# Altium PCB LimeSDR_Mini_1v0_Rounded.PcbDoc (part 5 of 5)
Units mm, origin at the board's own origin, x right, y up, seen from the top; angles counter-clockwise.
Board outline 69.3 x 52.3 mm, 8 copper layers (Top, L2, L3, L4, L5, L6, L7, Bottom), stack 1.555 mm thick; 371 components, 281 nets, 1644 pads, 778 vias.
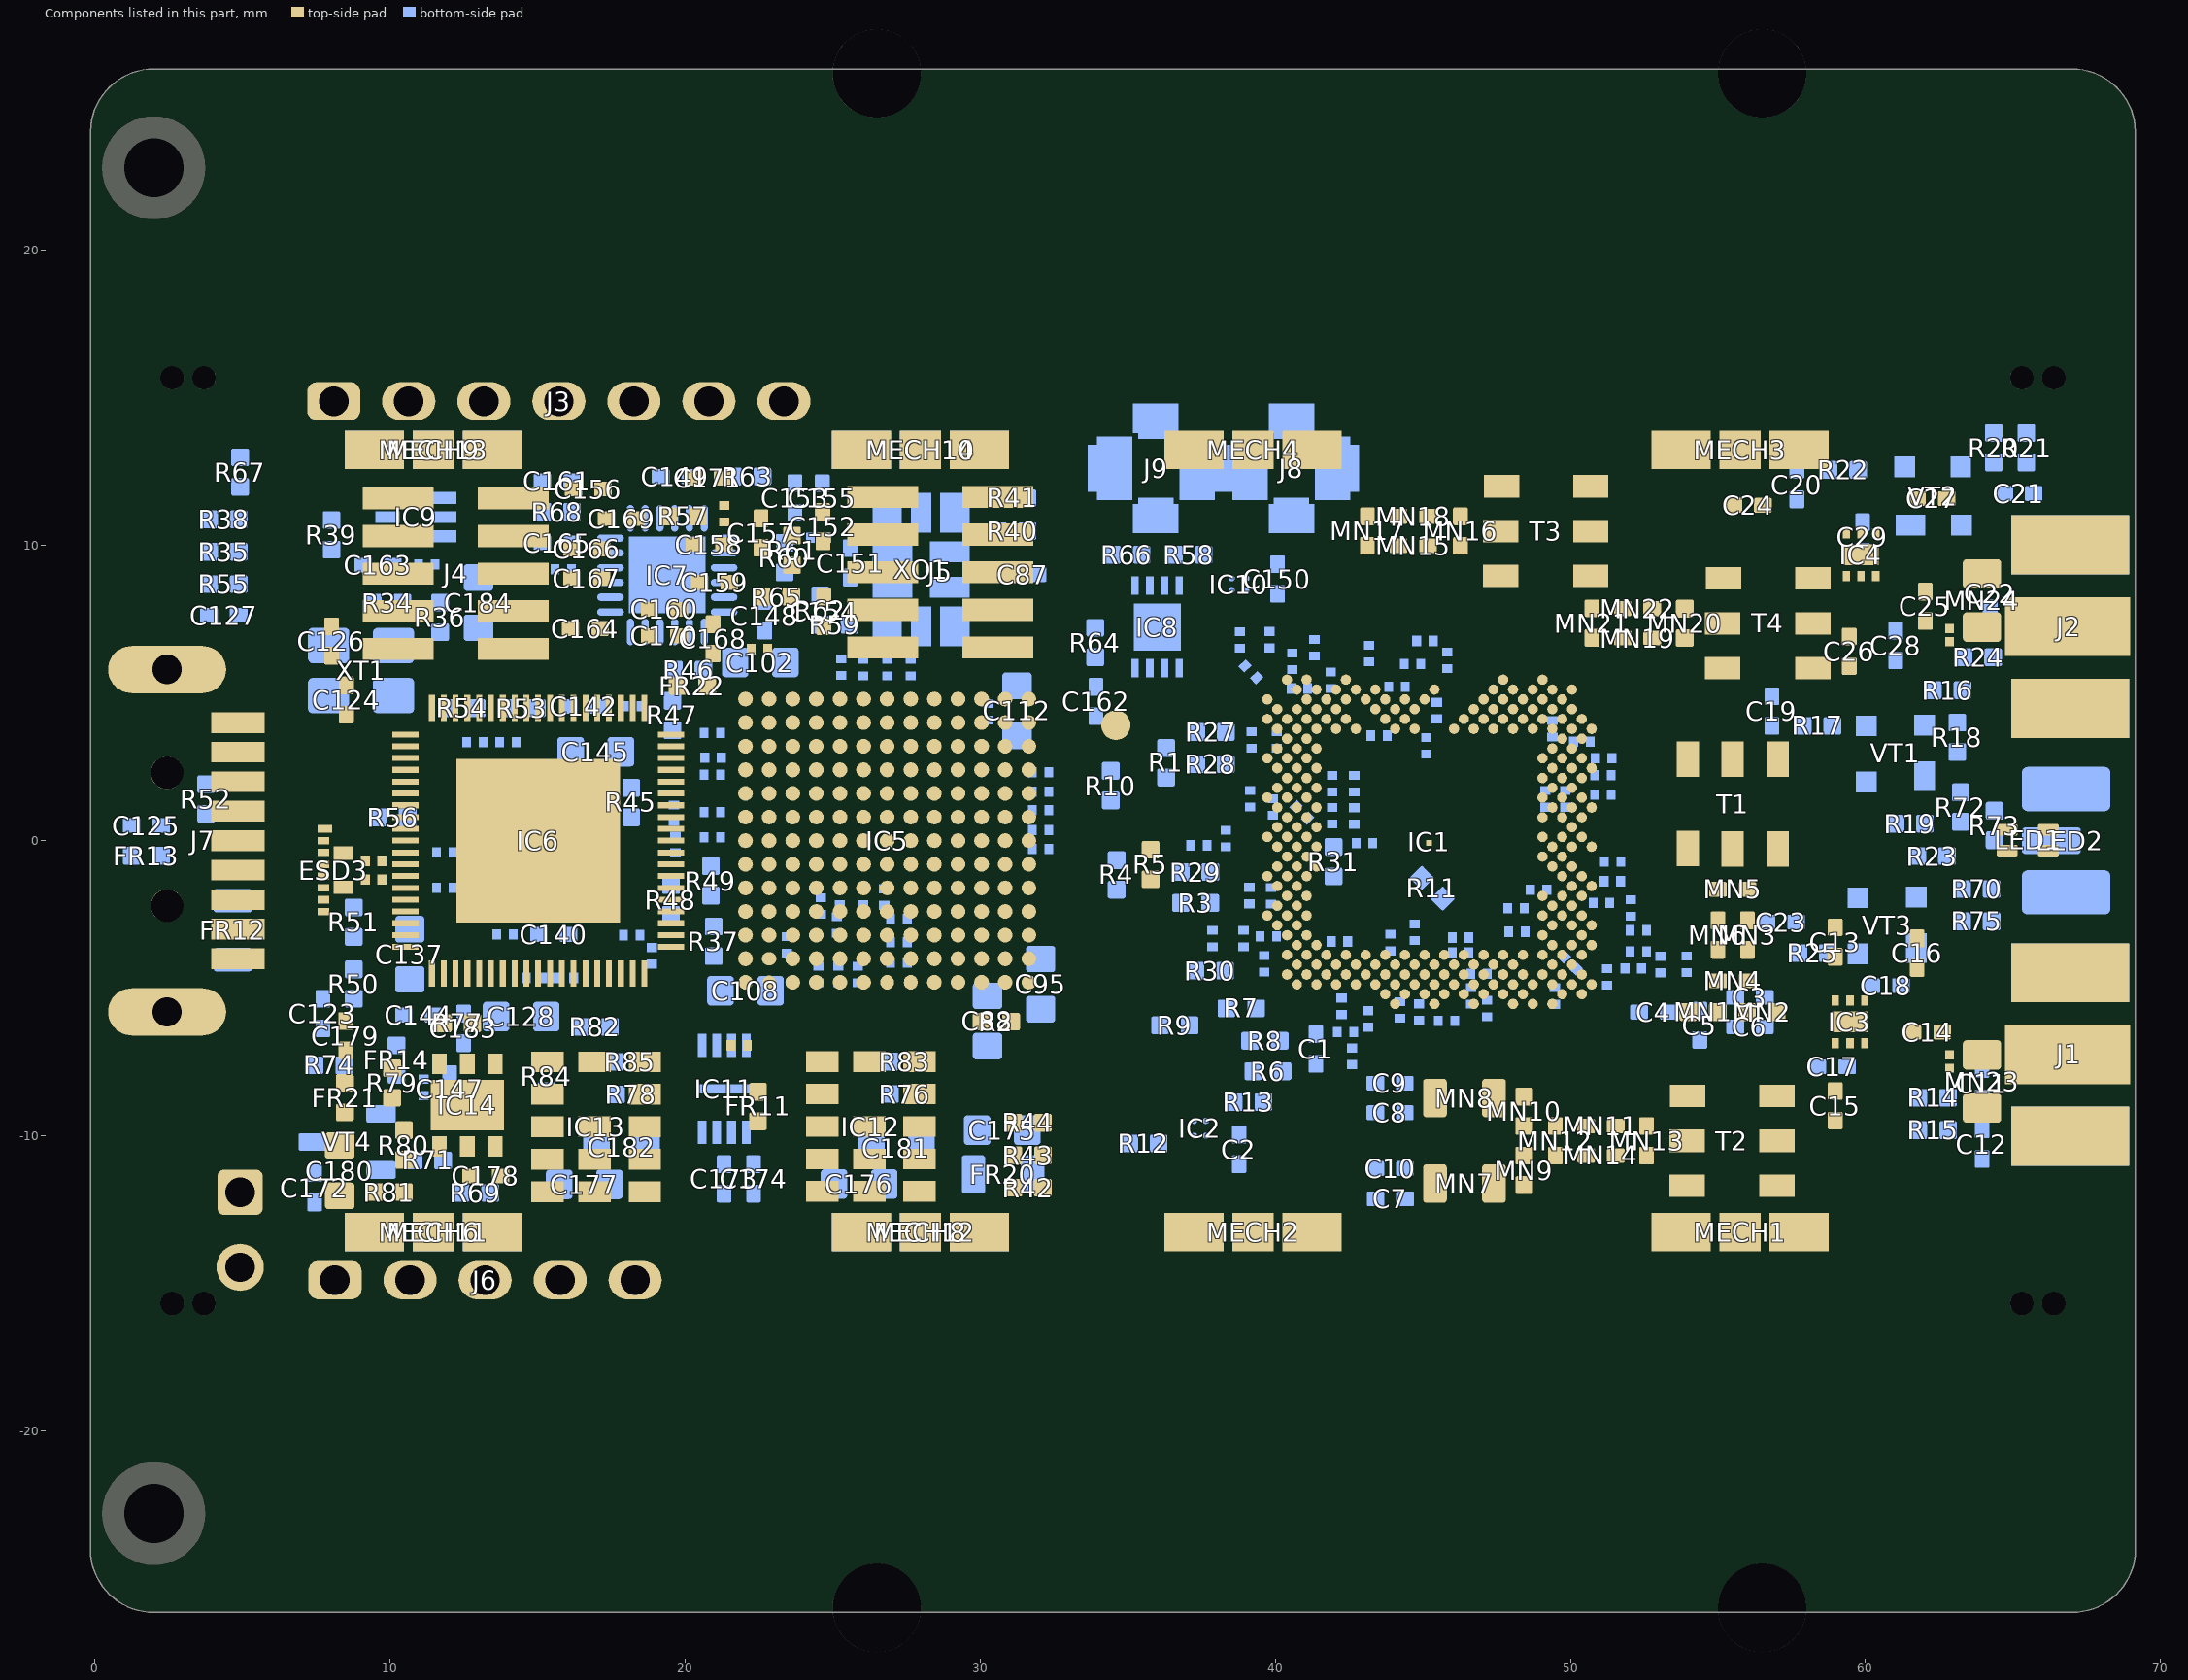
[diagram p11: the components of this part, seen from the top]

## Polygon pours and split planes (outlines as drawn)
GND on L5 "GND_L05_P033" (solid, remove dead copper, pour order 33): 0,-13.685 0,13.685 cw(c2,13.685) 2,15.685 67,15.685 cw(c67,13.685) 69,13.685 69,-13.685 cw(c67,-13.685) 67,-15.685 2,-15.685 cw(c2,-13.685)
VCC1P8_LMS on L5 "VCC1P8_LMS_L05_P026" (solid, remove dead copper, pour order 26): 31.65,-7.335 36.9,-7.335 37.275,-7.71 37.901,-7.71 38.276,-7.335 49.897,-7.335 51.175,-6.057 51.175,2.74 47.875,6.04 39.1,6.04 38.05,7.09 38.05,7.49 38.7,8.14 49.25,8.14 57.25,0.14 57.25,-6.185 55.875,-7.56 55.875,-9.435 52.425,-12.885 35.4,-12.885 31.275,-8.76 31.275,-7.71
GND on L3 "GND_L03_P031" (solid, remove dead copper, pour order 31): 0,-13.685 0,13.685 cw(c2,13.685) 2,15.685 67,15.685 cw(c67,13.685) 69,13.685 69,-13.685 cw(c67,-13.685) 67,-15.685 2,-15.685 cw(c2,-13.685)
VCC3P3 on L3 "VCC3P3_L03_P027" (solid, remove dead copper, pour order 27): 18.625,-11.885 19.756,-11.885 21.45,-10.191 21.45,-2.2 22.99,-0.66 26.65,-0.66 28.475,1.165 28.475,3.717 34.875,10.117 34.875,10.415 34.6,10.69 33.075,10.69 32.525,10.14 28.55,10.14 25.675,7.265 19.7,7.265 16.835,4.4 10.81,4.4 9.65,3.24 9.65,-4.385 11.55,-6.285 12.15,-6.285 14.075,-8.21 14.075,-9.441 15.044,-10.41 17.15,-10.41
VDIO_LMS on L3 "VDIO_LMS_L03_P028" (solid, remove dead copper, pour order 28): 31.05,-12.585 31.05,-9.96 32.625,-8.385 32.625,-7.635 31.525,-6.535 31.525,-2.435 37.475,3.515 38.4,3.515 41.925,-0.01 41.925,-3.635 35.9,-9.66 35.9,-10.26 33.2,-12.96 31.425,-12.96
GND on L2 "GND_L02_P030" (solid, remove dead copper, pour order 30): 0,-13.685 0,13.685 cw(c2,13.685) 2,15.685 67,15.685 cw(c67,13.685) 69,13.685 69,-13.685 cw(c67,-13.685) 67,-15.685 2,-15.685 cw(c2,-13.685)
USB_GND on L2 "USB_GND_L02_P029" (solid, remove dead copper, pour order 29): 10,-6.935 11.175,-5.76 11.175,-2.46 11.175,3.49 10.05,4.615 6.075,4.615 2.125,4.615 1.25,3.74 1.25,-5.185 3,-6.935
no net on Top "Top Layer-No Net" (none, pour order 39): 180,50
GND on Top "Top Layer-No Net" (solid, pour order 37): 0,-23.685 ccw(c2,-23.685) 2,-25.685 67,-25.685 ccw(c67,-23.685) 69,-23.685 69,-15.685 0,-15.685
GND on Top "Top Layer-No Net" (solid, pour order 38): -0.038,-24.244 cw(c0.095,-24.175) -0.055,-24.175 -0.055,24.025 cw(c0.095,24.025) -0.05,24.065 cw(c2.1,24.025) 2.1,26.175 67.09,26.175 cw(c67.09,24.025) 69.24,24.065 cw(c69.095,24.025) 69.245,24.025 69.245,-24.175 cw(c69.095,-24.175) 69.228,-24.244 cw(c67.095,-23.975) 67.095,-26.125 2.095,-26.125 cw(c2.095,-23.975)
GND on L4 "GND_L04_P032" (solid, remove dead copper, pour order 32): 0,-13.685 0,13.685 cw(c2,13.685) 2,15.685 67,15.685 cw(c67,13.685) 69,13.685 69,-13.685 cw(c67,-13.685) 67,-15.685 2,-15.685 cw(c2,-13.685)
GND on L6 "GND_L06_P034" (solid, remove dead copper, pour order 34): 0,-13.685 0,13.685 cw(c2,13.685) 2,15.685 67,15.685 cw(c67,13.685) 69,13.685 69,-13.685 cw(c67,-13.685) 67,-15.685 2,-15.685 cw(c2,-13.685)
GND on L7 "GND_L07_P035" (solid, remove dead copper, pour order 35): 0,-13.685 0,13.685 cw(c2,13.685) 2,15.685 67,15.685 cw(c67,13.685) 69,13.685 69,-13.685 cw(c67,-13.685) 67,-15.685 2,-15.685 cw(c2,-13.685)
GND on Bottom "GND_L08_P036" (solid, remove dead copper, pour order 36): 0,-13.685 0,13.685 cw(c2,13.685) 2,15.685 67,15.685 cw(c67,13.685) 69,13.685 69,-13.685 cw(c67,-13.685) 67,-15.685 2,-15.685 cw(c2,-13.685)
no net on TopSolder "Top Layer-No Net" (none): 0,-23.685 ccw(c2,-23.685) 2,-25.685 67,-25.685 ccw(c67,-23.685) 69,-23.685 69,-15.685 0,-15.685
no net on Mechanical2 "Top Layer-No Net" (none): 180,50
no net on Mechanical2 "Top Layer-No Net" (none): 102,48
no net on Mechanical2 "Top Layer-No Net" (none): 102,48
no net on Mechanical2 "Top Layer-No Net" (none): 102,48

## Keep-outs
KeepOutLayer:
  lines w0.1: 113.85,-33.86 ccw(c115.85,-33.86) 115.85,-35.86 180.85,-35.86 ccw(c180.85,-33.86) 182.85,-33.86 182.85,-25.86 113.85,-25.86 113.85,-33.86
  lines w0.3: -22.525,55.85 -22.525,104.05 ; -22.525,56.05 ccw(c-20.525,56.05) -20.525,54.05 44.475,54.05 ccw(c44.475,56.05) 46.475,56.05 ; -22.52,104.05 cw(c-20.52,104.05) -20.52,106.05 44.47,106.05 cw(c44.47,104.05) 46.47,104.05 ; 0,-24.2 0,24 ; 0,-24 ccw(c2,-24) 2,-26 67,-26 ccw(c67,-24) 69,-24 ; 0.005,24 cw(c2.005,24) 2.005,26 66.995,26 cw(c66.995,24) 68.995,24 ; 46.475,55.85 46.475,104.05 ; 69,-24.2 69,24 ; 113.85,13.51 cw(c115.85,13.51) 115.85,15.51 ; 115.855,15.515 180.845,15.515 ; 180.85,15.51 cw(c180.85,13.51) 182.85,13.51

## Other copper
Top:
  region net GND: 64.7,-9.01 64.7,-12.485 67.55,-12.485 68.95,-11.085 68.95,-9.01
  region net GND: 64.7,5.49 64.7,2.29 68.071,2.29 68.95,3.169 68.95,5.49
  region net GND: 64.7,9.015 64.7,12.49 67.55,12.49 68.95,11.09 68.95,9.015
  region net GND: 64.7,-5.485 64.7,-2.01 67.55,-2.01 68.95,-3.41 68.95,-5.485
  region net NetC21_2: 63.3,9.34 63.3,9.565 64.125,10.39 64.4,10.39 64.6,10.19 64.6,9.34
  region net NetC11_2: 63.3,-9.36 63.3,-9.71 63.475,-9.885 64.425,-9.885 64.6,-9.71 64.6,-9.36
  region net GND: 52.9,3.865 52.9,1.657 54.642,1.657 54.642,3.865
  region net VDIO_LMS: 8.8,-8.91 8.1,-8.91 7.8,-9.21 7.8,-10.085 8.8,-10.085
  region net GND: 13.025,-7.21 13.175,-7.36 13.175,-8.11 13.925,-8.11 13.925,-9.81 11.375,-9.81 11.375,-8.11 12.15,-8.11 12.15,-7.21
  region net VCC3P3: 14.575,-9.46 14.575,-10.035 13.9,-10.71 13.325,-10.71 13.325,-10.01 13.9,-10.01 14.125,-9.785 14.125,-9.46
  region net VCC3P3: 12.5,-6.535 12.525,-6.535 13.325,-7.335 13.325,-7.91 13.875,-7.91 14.075,-8.11 14.075,-9.96 14.575,-9.46 14.575,-8.035 14.05,-7.51 14.05,-6.86 13.025,-5.835 12.5,-5.835
  region net GND: 56.845,-7.685 55.96,-8.57 55.96,-8.795 56.21,-9.045 57.785,-9.045 58.035,-8.795 58.035,-8.57 57.15,-7.685
  region net GND: 49.15,12.99 49.55,12.59 49.55,12.015 49.95,11.615 51.425,11.615 52.175,12.365 52.175,12.99
  region net GND: 57.925,9.715 57.175,8.965 57.175,8.74 57.425,8.49 58.825,8.49 58.825,9.665 58.775,9.715
  pour cut-out: 43.477,-13.01 42.1,-11.633 42.1,-7.51 43.1,-6.51 44.1,-6.51 45.925,-4.685 48.54,-4.685 49.515,-5.66 51.65,-5.66 52.525,-4.785 52.525,0.94 53.075,1.49 54.6,1.49 54.825,1.715 54.825,4.215 54.325,4.715 51.96,4.715 50.66,3.415 45.45,3.415 45.45,4.715 43.325,6.84 40.9,6.84 40.125,7.615 40.125,11.09 42.025,12.99 63.8,12.99 66.275,10.515 69,10.515 69,3.015 64.75,3.015 64.35,2.615 63.6,2.615 62,1.015 62,-0.685 63.625,-2.31 64.35,-2.31 65.45,-3.41 69,-3.41 69,-6.96 69,-10.535 66.25,-10.535 63.775,-13.01
  region net VDIO_LMS: 7.8,-10.61 7.8,-11.285 7.925,-11.41 8.675,-11.41 8.8,-11.285 8.8,-10.61
  region net VCC1P8: 21.125,11.19 20.95,11.365 20.95,11.89 21,11.94 21.875,11.94 21.925,11.89 21.925,11.39 21.725,11.19
  pour cut-out: 5.075,-4.46 9.075,-4.46 10.325,-3.21 10.325,3.015 8.15,3.015 6.58,1.445 5.855,1.445 5.075,0.665
  region net VCC1P8_LMS: 45.825,-12.277 44.8,-12.277 44.625,-12.102 44.625,-11.152 44.825,-10.952 45.825,-10.952
  region net VCC1P8_LMS: 45.825,-8.06 44.8,-8.06 44.625,-8.235 44.625,-9.185 44.825,-9.385 45.825,-9.385
  region net VCC3P3A: 21.95,-8.835 22.125,-9.01 22.875,-9.01 23.2,-8.685 23.2,-6.76 23.075,-6.635 22.075,-6.635 21.95,-6.76
  region net PG_VCC1P8: 27.386,-8.945 28.736,-8.945 28.936,-8.745 28.936,-8.585 27.386,-8.585
  region net PG_VCC1P8: 27.386,-8.225 28.736,-8.225 28.936,-8.425 28.936,-8.585 27.386,-8.585
  region net NetIC12_11: 27.386,-7.845 28.736,-7.845 28.936,-7.645 28.936,-7.485 27.386,-7.485
  region net NetIC12_11: 27.386,-7.125 28.736,-7.125 28.936,-7.325 28.936,-7.485 27.386,-7.485
  region net VCC5P0_USB: 25.214,-10.425 23.864,-10.425 23.664,-10.625 23.664,-10.785 25.214,-10.785
  region net VCC5P0_USB: 25.214,-11.145 23.864,-11.145 23.664,-10.945 23.664,-10.785 25.214,-10.785
  region net VCC5P0_USB: 25.214,-11.525 23.864,-11.525 23.664,-11.725 23.664,-11.885 25.214,-11.885
  region net VCC5P0_USB: 25.214,-12.245 23.864,-12.245 23.664,-12.045 23.664,-11.885 25.214,-11.885
  region net VCC5P0_USB: 23.864,-11.145 23.864,-11.525 25.214,-11.525 25.214,-11.145
  region net VCC1P8: 28.736,-11.145 28.736,-11.525 27.386,-11.525 27.386,-11.145
  region net VCC1P8: 27.386,-12.245 28.736,-12.245 28.936,-12.045 28.936,-11.885 27.386,-11.885
  region net VCC1P8: 27.386,-11.525 28.736,-11.525 28.936,-11.725 28.936,-11.885 27.386,-11.885
  region net VCC1P8: 27.386,-11.145 28.736,-11.145 28.936,-10.945 28.936,-10.785 27.386,-10.785
  region net VCC1P8: 27.386,-10.425 28.736,-10.425 28.936,-10.625 28.936,-10.785 27.386,-10.785
  region net NetIC13_10: 18.075,-8.955 19.425,-8.955 19.625,-8.755 19.625,-8.595 18.075,-8.595
  region net NetIC13_10: 18.075,-8.235 19.425,-8.235 19.625,-8.435 19.625,-8.595 18.075,-8.595
  region net NetIC13_11: 18.075,-7.855 19.425,-7.855 19.625,-7.655 19.625,-7.495 18.075,-7.495
  region net NetIC13_11: 18.075,-7.135 19.425,-7.135 19.625,-7.335 19.625,-7.495 18.075,-7.495
  region net NetIC13_1: 15.903,-7.135 14.553,-7.135 14.353,-7.335 14.353,-7.495 15.903,-7.495
  region net NetIC13_1: 15.903,-7.855 14.553,-7.855 14.353,-7.655 14.353,-7.495 15.903,-7.495
  region net VCC5P0_USB: 15.903,-10.435 14.553,-10.435 14.353,-10.635 14.353,-10.795 15.903,-10.795
  region net VCC5P0_USB: 15.903,-11.155 14.553,-11.155 14.353,-10.955 14.353,-10.795 15.903,-10.795
  region net VCC5P0_USB: 15.903,-11.535 14.553,-11.535 14.353,-11.735 14.353,-11.895 15.903,-11.895
  region net VCC5P0_USB: 15.903,-12.255 14.553,-12.255 14.353,-12.055 14.353,-11.895 15.903,-11.895
  region net VCC5P0_USB: 14.553,-11.155 14.553,-11.535 15.903,-11.535 15.903,-11.155
  region net VCC3P3: 19.425,-11.155 19.425,-11.535 18.075,-11.535 18.075,-11.155
  region net VCC3P3: 18.075,-12.255 19.425,-12.255 19.625,-12.055 19.625,-11.895 18.075,-11.895
  region net VCC3P3: 18.075,-11.535 19.425,-11.535 19.625,-11.735 19.625,-11.895 18.075,-11.895
  region net VCC3P3: 18.075,-11.155 19.425,-11.155 19.625,-10.955 19.625,-10.795 18.075,-10.795
  region net VCC3P3: 18.075,-10.435 19.425,-10.435 19.625,-10.635 19.625,-10.795 18.075,-10.795
  region net USB_VBUS: 5.75,-3.36 3.975,-3.36 3.8,-3.535 3.225,-3.535 3,-3.31 3,-3.01 5.75,-3.01
  region net USB_VBUS: 5.75,-2.64 3.975,-2.64 3.8,-2.465 3.225,-2.465 3,-2.69 3,-2.99 5.75,-2.99
  region net USB_VBUS: 3,-3.31 3,-2.69 4.28,-2.69 4.3,-2.71 4.3,-3.285 4.275,-3.31
  region net GND: 25.375,-12.66 25.375,-12.01 25.5,-11.885 27.15,-11.885 27.15,-12.66
  region net GND: 25.375,-6.579 25.375,-7.36 25.5,-7.485 27.15,-7.485 27.15,-6.579
  region net GND: 16.064,-6.589 16.064,-7.37 16.189,-7.495 17.839,-7.495 17.839,-6.589
  region net GND: 16.011,-12.887 16.011,-12.022 16.136,-11.897 17.786,-11.897 17.786,-12.887
  region net GND: 48.675,-1.538 49.453,-1.538 49.475,-1.56 49.475,-1.36 48.7,-0.585 48.675,-0.585
  region net NetJ7_7: 4.85,0.34 4.025,0.34 3.875,0.49 3.625,0.49 3.525,0.39 3.525,0 4.85,0
  region net NetJ7_7: 4.85,-0.34 4.025,-0.34 3.875,-0.49 3.625,-0.49 3.525,-0.39 3.525,0 4.85,0
  region net TX1_1_A_P: 48.48,-5.778 48.427,-5.725 48.427,-5.583
  region net GND: 21.45,-4.41 21.45,-4.8 22.05,-4.8 21.66,-4.41
  region net NetIC14_4: 9.725,-8.41 9.725,-9.71 10.325,-10.31 10.75,-10.31 11.175,-10.735 11.925,-10.735 12,-10.66 12,-10.085 11.9,-9.985 11.375,-9.985 10.425,-9.035 10.425,-8.41
  region net VDIO_LMS_FPGA: 10.375,-8.01 10.375,-7.16 10.025,-6.81 8.175,-6.81 8.175,-8.21 8.475,-8.51 8.825,-8.51 9.325,-8.01
  region net VCC1P8_LMS: 53.675,-5.46 53.85,-5.285 54.12,-5.285 54.293,-5.458 54.293,-5.808 53.677,-5.808
  region net VCC1P8_LMS: 53.675,-6.156 53.854,-6.335 54.116,-6.335 54.293,-6.158 54.293,-5.808 53.677,-5.808
  region net VCC1P8_LMS: 57.31,-6.156 57.131,-6.335 56.87,-6.335 56.693,-6.158 56.693,-5.808 57.308,-5.808
  region net VCC1P8_LMS: 57.31,-5.46 57.135,-5.285 56.866,-5.285 56.693,-5.458 56.693,-5.808 57.308,-5.808
  region net GND: 63,-7.56 63.2,-7.76 63.2,-8.135 63.1,-8.235 62.7,-8.235 62.55,-8.085 62.55,-7.71 62.7,-7.56
  region net GND: 62.275,6.44 62.025,6.44 61.9,6.315 61.9,6.09 61.975,6.015 62.475,6.015 63.075,6.615 63.075,6.89 62.65,6.89 62.65,6.815
  region net GND: 3.4,3.365 5.75,3.365 5.75,2.64 3.4,2.64
L2:
  pour cut-out: 64.72,-6.248 64.72,-8.248 69,-8.248 69,-6.248
  pour cut-out: 63.3,6.74 63.3,7.74 64.6,7.74 64.6,6.74
  pour cut-out: 63.3,-7.76 63.3,-6.76 64.6,-6.76 64.6,-7.76
  pour cut-out: 46.575,9.68 45.96,9.68 45.96,10.305 46.575,10.305
  pour cut-out: 43.385,9.68 42.86,9.68 42.86,10.305 43.385,10.305
  pour cut-out: 43.385,11.3 42.86,11.3 42.86,10.675 43.385,10.675
  pour cut-out: 45.485,10.25 45.485,9.725 44.86,9.725 44.86,10.25
  pour cut-out: 43.865,10.25 43.865,9.725 44.49,9.725 44.49,10.25
  pour cut-out: 45.485,11.25 45.485,10.725 44.86,10.725 44.86,11.25
  pour cut-out: 43.865,11.25 43.865,10.725 44.49,10.725 44.49,11.25
  pour cut-out: 46.575,10.68 45.96,10.68 45.96,11.305 46.575,11.305
  pour cut-out: 54.15,7.555 53.535,7.555 53.535,8.18 54.15,8.18
  pour cut-out: 64.72,8.252 64.72,6.252 69,6.252 69,8.252
  pour cut-out: 57.59,5.451 57.59,6.251 58.815,6.251 58.815,5.451
  pour cut-out: 54.555,5.45 54.555,6.25 55.78,6.25 55.78,5.45
  pour cut-out: 54.58,8.49 54.58,9.29 55.805,9.29 55.805,8.49
  pour cut-out: 56.625,0.325 57.425,0.325 57.425,-0.9 56.625,-0.9
  pour cut-out: 53.585,0.35 54.385,0.35 54.385,-0.875 53.585,-0.875
  pour cut-out: 56.625,3.375 57.425,3.375 57.425,2.15 56.625,2.15
  pour cut-out: 57.61,-11.295 57.61,-12.095 56.385,-12.095 56.385,-11.295
  pour cut-out: 54.56,-11.295 54.56,-12.095 53.335,-12.095 53.335,-11.295
  pour cut-out: 54.585,-8.255 54.585,-9.055 53.36,-9.055 53.36,-8.255
  pour cut-out: 51.3,9.365 51.3,8.565 50.075,8.565 50.075,9.365
  pour cut-out: 48.275,12.405 48.275,11.605 47.05,11.605 47.05,12.405
  pour cut-out: 48.25,9.365 48.25,8.565 47.025,8.565 47.025,9.365
  region net USB_GND: 5.892,-6.935 10,-6.935 10.239,-6.696 10.239,-6.274 10.15,-6.185 5.825,-6.185 5.825,-6.868
  region net GND: 4.95,-7.685 4.95,-8.935 10.625,-8.935 10.625,-7.685
  pour cut-out: 48.125,-9.36 48.125,-9.985 48.75,-9.985 48.75,-9.36
  pour cut-out: 48.125,-10.36 48.125,-10.985 48.75,-10.985 48.75,-10.36
  pour cut-out: 49.225,-10.98 49.75,-10.98 49.75,-10.355 49.225,-10.355
  pour cut-out: 49.225,-9.36 49.75,-9.36 49.75,-9.985 49.225,-9.985
  pour cut-out: 52.325,-9.36 52.85,-9.36 52.85,-9.985 52.325,-9.985
  pour cut-out: 52.325,-10.98 52.85,-10.98 52.85,-10.355 52.325,-10.355
  pour cut-out: 50.225,-9.93 50.225,-9.405 50.85,-9.405 50.85,-9.93
  pour cut-out: 51.845,-9.93 51.845,-9.405 51.22,-9.405 51.22,-9.93
  pour cut-out: 50.225,-10.93 50.225,-10.405 50.85,-10.405 50.85,-10.93
  pour cut-out: 51.845,-10.93 51.845,-10.405 51.22,-10.405 51.22,-10.93
  pour cut-out: 56.26,-2.39 55.735,-2.39 55.735,-3.015 56.26,-3.015
  pour cut-out: 56.26,-4.01 55.735,-4.01 55.735,-3.385 56.26,-3.385
  pour cut-out: 55.26,-2.39 54.735,-2.39 54.735,-3.015 55.26,-3.015
  pour cut-out: 55.26,-4.01 54.735,-4.01 54.735,-3.385 55.26,-3.385
  pour cut-out: 56.31,-1.91 56.31,-1.385 55.685,-1.385 55.685,-1.91
  pour cut-out: 54.69,-1.91 54.69,-1.385 55.315,-1.385 55.315,-1.91
  pour cut-out: 54.69,-5.01 54.69,-4.485 55.315,-4.485 55.315,-5.01
  pour cut-out: 56.31,-5.01 56.31,-4.485 55.685,-4.485 55.685,-5.01
  pour cut-out: 55.69,-6.11 56.315,-6.11 56.315,-5.485 55.69,-5.485
  pour cut-out: 54.69,-6.11 55.315,-6.11 55.315,-5.485 54.69,-5.485
  pour cut-out: 51.44,8.125 51.44,7.6 52.065,7.6 52.065,8.125
  pour cut-out: 53.06,8.125 53.06,7.6 52.435,7.6 52.435,8.125
  pour cut-out: 51.44,7.125 51.44,6.6 52.065,6.6 52.065,7.125
  pour cut-out: 53.06,7.125 53.06,6.6 52.435,6.6 52.435,7.125
  pour cut-out: 50.96,8.175 50.435,8.175 50.435,7.55 50.96,7.55
  pour cut-out: 50.96,6.555 50.435,6.555 50.435,7.18 50.96,7.18
  pour cut-out: 54.15,6.555 53.535,6.555 53.535,7.18 54.15,7.18
L3:
  pour cut-out: 64.72,-6.248 64.72,-8.248 69,-8.248 69,-6.248
  pour cut-out: 63.3,6.74 63.3,7.74 64.6,7.74 64.6,6.74
  pour cut-out: 63.3,-7.76 63.3,-6.76 64.6,-6.76 64.6,-7.76
  pour cut-out: 64.72,8.252 64.72,6.252 69,6.252 69,8.252
  region net VCC5P0_USB: 5.075,-5.31 5.175,-5.41 5.975,-5.41 6.075,-5.31 6.075,-4.66 5.625,-4.21 5.075,-4.21
  region net VCC3P3A: 22.375,-7.11 23.15,-7.11 23.2,-7.06 23.2,-6.685 22.7,-6.185 22.475,-6.185 22.325,-6.335 22.325,-7.06
L4:
  pour cut-out: 64.72,-6.248 64.72,-8.248 69,-8.248 69,-6.248
  pour cut-out: 64.72,8.252 64.72,6.252 69,6.252 69,8.252
L5:
  pour cut-out: 64.72,-6.248 64.72,-8.248 68.92,-8.248 68.92,-6.248
  pour cut-out: 64.72,8.252 64.72,6.252 68.92,6.252 68.92,8.252
  region net AVDD_FT: 10.975,-6.535 10.85,-6.66 10.85,-7.56 10.975,-7.685 11.375,-7.685 11.5,-7.56 11.5,-6.66 11.375,-6.535
  text "A" at 0.575,-8.36 h0.7
  text "V" at 1.575,-8.36 h0.7
  text "L" at 1.05,-8.935 h0.7
  text "D" at 0.8,-10.56 h0.7
  text "R" at 1.35,-10.56 h0.7
L7:
  pour cut-out: 26.35,7.94 26.35,6.677 26.437,6.59 27.35,6.59 27.35,7.94
L6:
  region net VCC1P8: 21.075,11.515 20.95,11.64 20.95,11.815 21.437,12.302 21.825,11.915 21.825,11.615 21.725,11.515
  region net VCC3P3A: 22.375,-7.11 23.15,-7.11 23.2,-7.06 23.2,-6.685 22.7,-6.185 22.475,-6.185 22.25,-6.41 22.25,-6.985
Bottom:
  region net GND: 64.598,-9.08 64.598,-8.764 68.95,-8.764 68.95,-9.08
  region net GND: 64.691,-9.08 64.691,-11.272 68.95,-11.272 68.95,-9.08
  region net GND: 64.691,-3.224 64.691,-5.732 68.95,-5.732 68.95,-3.224
  region net GND: 64.598,5.42 64.598,5.736 68.95,5.736 68.95,5.42
  region net GND: 11.8,-5.323 11.562,-5.56 11.175,-5.56 11.175,-6.26 11.275,-6.36 12.85,-6.36 12.875,-6.335 12.875,-5.685 12.85,-5.685 12.7,-5.535 12.177,-5.535 12.009,-5.366
  region net VCC1P8_LMS: 44.042,-9.393 44.133,-9.485 44.892,-9.485 45.1,-9.277 45.1,-8.718 44.042,-8.718
  region net VCC1P8_LMS: 44.042,-8.043 44.125,-7.96 44.9,-7.96 45.1,-8.16 45.1,-8.718 44.042,-8.718
  region net VCC5P0_USB: 13.1,-11.585 14.3,-11.585 14.438,-11.448 14.575,-11.448 14.575,-12.105 14.395,-12.285 13.1,-12.285
  region net AVDD_FT: 9.925,-8.235 12.225,-8.235 12.275,-8.185 12.275,-7.479 11.459,-6.785 11.025,-6.785 10.95,-6.86 10.95,-7.26 10.8,-7.41 9.875,-7.41 9.875,-8.185
  region net GND: 10.017,-11.86 8.9,-11.86 8.9,-11.163 8.84,-11.103 9.083,-10.86 10.385,-10.86 10.385,-11.492
  region net NetC50_1: 51.875,-2.86 51.625,-3.11 50.346,-3.11 50.346,-3.281 51.025,-3.96 52.2,-3.96 52.2,-2.86
  region net GND: 20.18,-8.56 20.18,-9.19 20.25,-9.26 20.675,-9.26 20.75,-9.185 20.75,-8.935 20.95,-8.735 22.55,-8.735 22.875,-8.41 22.875,-8.185 21.24,-8.185 20.968,-7.914
  region net VCC3P3: 21.05,2.065 21.05,2.99 20.875,3.165 21.248,3.165 21.345,3.068 21.345,2.38 21.345,2.065
  region net GND: 15.639,10.777 15.639,10.604 15.475,10.44 15.25,10.44 15.2,10.49 15.2,10.64 15.225,10.665 15.527,10.665
  region net GND: 8.925,9.09 8.8,9.215 8.8,9.34 8.725,9.415 8.425,9.415 8.177,9.167 8.177,10.015 9.4,10.015 9.4,9.09
  region net GND: 25.05,5.015 24.7,5.015 24.025,5.69 24.025,6.415 24.2,6.59 26.05,6.59 26.225,6.415 27.475,6.415 27.475,5.99 24.975,5.99 24.85,5.865 24.85,5.2 25.04,5.2 25.05,5.19
  region net GND: 18.15,6.948 18.65,6.948 18.65,8.065 18.15,7.565 18.15,7.088
  region net GND: 20.125,7.765 20.5,7.39 20.5,6.565 20.85,6.215 21.875,6.215 21.95,6.29 21.95,7.04 21.525,7.465 20.925,7.465 20.625,7.765
  region net GND: 20.18,-8.006 20.18,-8.56 21.5,-8.56 21.5,-8.485 20.95,-7.935 20.251,-7.935
  region net VCC3P3: 19.6,-12.08 19.9,-11.78 19.9,-10.18 19.6,-9.88
  region net GND: 27.55,6.549 27.55,6.245 27.65,6.145 27.042,6.141 27.125,6.245 27.45,6.245 27.45,6.549
  region net VCC1P8_LMS: 31.375,-12.06 32.175,-12.06 32.5,-11.735 32.5,-7.835 32.05,-7.385 31.375,-7.385 30.925,-7.835 30.925,-11.61
  region net VCC1P8: 28.34,-12.11 30.125,-12.11 30.35,-11.885 30.35,-10.86 30.025,-10.535 29.275,-10.535 28.3,-9.56 27.575,-9.56 27.575,-11.345
  region net VDIO_LMS_LMK: 16.55,8.59 16.95,8.59 17.075,8.465 17.8,8.465 17.925,8.34 17.925,8.19 17.85,8.115 16.925,8.115 16.85,8.19 16.6,8.19 16.5,8.29 16.5,8.54
  region net VDIO_LMS: 35.425,-1.035 35.425,-0.61 35.55,-0.485 35.95,-0.485 36.225,-0.76 36.225,-1.035
  region net USB_VBUS: 5.75,-2.01 5.375,-1.635 3.975,-1.635 3.55,-1.635 3.125,-2.06 3.125,-2.485 3,-2.61 3,-3.41 3.125,-3.535 3.825,-3.535 4.15,-3.21 5.625,-3.21 5.75,-3.335
  region net VCC5P0_USB: 4.025,-3.635 4.025,-4.76 4.75,-5.485 5.825,-5.485 5.975,-5.335 5.975,-4.11 5.5,-3.635
  region net USB_VBUS: 5.75,-3.335 5.95,-3.335 7.05,-4.435 7.75,-4.435 8.125,-4.06 8.125,-2.56 7.575,-2.01 5.75,-2.01
  pour cut-out: 4.25,-1.685 4.25,3.815 4.75,4.315 8.25,4.315 8.75,3.815 8.75,-1.435 8.25,-1.935 4.5,-1.935
  region net NetC45_1: 38.251,6.397 38.251,6.039 38.63,5.66 38.988,5.66
  region net VCC1P8_LMS: 53.025,-5.46 53.208,-5.277 54.108,-5.277 54.283,-5.452 54.283,-5.81 53.025,-5.81
  region net VCC1P8_LMS: 53.025,-6.16 53.208,-6.343 54.108,-6.343 54.407,-6.045 54.407,-5.81 53.025,-5.81
  region net VCC1P8_LMS: 44.042,-10.943 44.125,-10.86 44.9,-10.86 45.1,-11.06 45.1,-11.618 44.042,-11.618
  region net USB_VBUS: 7.8,-3.735 8.125,-4.06 8.125,-4.56 8.625,-5.06 9.125,-5.06 9.275,-5.21 9.275,-5.71 9.125,-5.86 7.45,-5.86 6.725,-5.135 6.725,-3.735
  region net VDIO_LMS: 37.091,2.374 36.55,2.915 36.55,3.54 37.046,4.036 37.626,4.036 37.775,3.887 37.775,3.013
  region net VCC5P0_USB: 14.525,-10.555 14.525,-9.935 15.05,-9.41 15.375,-9.41 15.95,-9.985 15.95,-10.555
  region net VCC5P0_USB: 25.486,-10.77 25.261,-10.545 23.836,-10.545 23.686,-10.695 23.686,-11.995 23.836,-12.145 25.311,-12.145 25.486,-11.97
  region net NetIC12_11: 27.636,-7.125 28.736,-7.125 28.936,-7.325 28.936,-7.485 27.636,-7.485
  region net NetIC12_11: 27.636,-7.845 28.736,-7.845 28.936,-7.645 28.936,-7.485 27.636,-7.485
  region net PG_VCC1P8: 27.575,-8.945 28.736,-8.945 28.936,-8.745 28.936,-8.585 27.575,-8.585
  region net PG_VCC1P8: 27.575,-8.225 28.736,-8.225 28.936,-8.425 28.936,-8.585 27.575,-8.585
  region net VCC5P0_USB: 16.175,-10.78 15.95,-10.555 14.525,-10.555 14.375,-10.705 14.375,-12.005 14.525,-12.155 16,-12.155 16.175,-11.98
  region net NetIC13_11: 18.325,-7.135 19.425,-7.135 19.625,-7.335 19.625,-7.495 18.325,-7.495
  region net NetIC13_11: 18.325,-7.855 19.425,-7.855 19.625,-7.655 19.625,-7.495 18.325,-7.495
  region net NetIC13_10: 18.264,-8.955 19.425,-8.955 19.625,-8.755 19.625,-8.595 18.264,-8.595
  region net NetIC13_10: 18.264,-8.235 19.425,-8.235 19.625,-8.435 19.625,-8.595 18.264,-8.595
  region net VCC3P3: 18.975,-9.255 19.6,-9.88 19.6,-12.08 19.175,-12.505 18.25,-12.505 18.25,-9.28 18.275,-9.255
  region net NetC163_1: 9.5,10.515 9.5,9.34 9.75,9.09 11.075,9.09 11.175,9.19 11.175,9.815 10.475,10.515
  region net GND: 44.851,4.147 45.001,4.297 45.601,4.297 45.601,3.972 45.426,3.797 44.976,3.797
  region net NetC75_1: 44.676,4.922 44.676,5.447 44.776,5.547 45.051,5.547 45.076,5.522 45.076,5.222 44.851,4.997 44.733,4.879
  region net VDIO_LMS: 41.226,-1.453 41.776,-0.903 42.026,-0.903 42.026,-1.428 41.626,-1.828 41.426,-1.828 41.226,-1.628
  region net GND: 40.398,2.802 40.398,1.969 40.201,1.772 39.276,1.772 39.251,1.797 39.251,2.997 39.351,3.097 40.102,3.097
  region net GND: 45.976,-2.303 45.976,-2.828 47.601,-2.828 47.601,-2.303
  region net NetC45_1: 38.988,5.66 39.501,6.172 39.501,6.472 39.501,6.597 39.401,6.697 38.276,6.697 38.251,6.672 38.251,6.397
  region net VCC3P3: 15.225,-5.36 14.975,-5.11 14.975,-4.46 15.85,-4.46 15.85,-5.11 15.6,-5.36
  region net VCC3P3: 18.375,-2.96 18.325,-3.01 18.325,-3.435 18.675,-3.785 19.05,-3.785 19.05,-2.96
  region net VCC3P3: 20.385,0.2 20.135,-0.05 19.485,-0.05 19.485,0.79 19.825,0.79 20.044,0.615 20.385,0.615 20.385,0.255
  region net VCC3P3: 13.625,4.06 13.875,3.81 13.875,3.16 13,3.16 13,3.81 13.25,4.06
  region net VCC3P3_CLK: 11.375,9.74 11.55,9.915 11.925,9.915 12.6,9.24 12.6,8.69 11.675,8.69 11.375,8.99
  region net VD10_FT: 10.575,-7.235 10.575,-6.935 10.775,-6.735 10.775,-4.35 10.675,-4.25 9.86,-4.25 9.55,-4.56 9.55,-6.91 9.9,-7.26 10.55,-7.26
  region net NetJ7_7: 4.125,1.215 4.2,1.14 4.2,-0.385 4.125,-0.46 3.425,-0.46 3.35,-0.385 3.35,1.14 3.425,1.215
  region net GND: 42.953,0.704 43.528,0.129 43.528,-0.271 43.378,-0.421 42.503,-0.421 42.503,-1.471 41.475,-2.499 41.475,-2.66 45.353,-2.66 45.353,-2.321 44.453,-1.421 44.453,-1.171 44.878,-0.746 45.053,-0.746 45.828,-1.521 46.478,-2.171 47.478,-2.171 47.653,-1.996 48.278,-1.996 48.278,-1.457 48.753,-0.982 48.753,4.987 47.75,5.99 46.175,5.99 46.175,4.665 45.85,4.34 45.85,3.44 45.414,3.004 44.628,3.004 44.428,3.204 42.953,3.204
  region net GND: 12.142,2.737 17,2.74 17.714,2.026 17.714,-2.646 17.671,-2.689 12.153,-2.689
  region net GND: 48.861,-0.884 48.861,1.004 48.8,1.065 48.75,1.065 48.65,0.965 48.753,0.862 48.753,-0.982
  region net VDIO_LMS: 37.775,-9.835 37.64,-9.845 37.5,-9.985 37.5,-10.11
  region net GND: 65.025,-3.945 65.025,-3.11 68.796,-3.11 68.796,-3.945
  region net GND: 64.598,4.645 64.598,5.465 68.796,5.465 68.796,4.645
  region net GND: 64.598,4.645 64.598,2.69 68.95,2.69 68.95,4.645
  region net GND: 64.598,9.085 64.598,8.768 68.95,8.768 68.95,9.085
  region net GND: 64.598,8.94 64.598,10.663 65.155,11.22 68.95,11.22 68.95,8.94
  region net VCC1P8_LMS: 44.042,-12.293 44.133,-12.385 44.892,-12.385 45.1,-12.177 45.1,-11.618 44.042,-11.618
  region net VCC1P8_LMS: 56.285,-6.66 56.8,-6.66 57.2,-6.26 57.2,-5.36 56.8,-4.96 56.285,-4.96
  region net NetC11_2: 62.5,-8.36 64.225,-8.36 64.425,-8.56 64.425,-9.96 64.228,-10.157 62.5,-10.157
  region net NetC21_2: 64.875,11.415 64.525,11.415 64,11.94 64,13.115 65.8,13.115 65.8,12.59 65.2,11.99 65.2,11.74
  region net GND: 27.414,-12.356 27.229,-12.356 26.975,-12.61 26.225,-12.61 26.225,-12.51 26.725,-12.01 27.55,-12.01 27.55,-12.22
  region net NetC153_2: 24.1,9.79 24.4,10.09 24.4,10.44 23.925,10.915 23.5,10.915 23.075,10.49 23.075,10.09 23.375,9.79
  region net GND: 36.625,8.965 37.25,8.965 37.45,8.765 37.45,5.615 37.35,5.515 35.6,5.515 35.6,6.165 36.95,6.165 36.95,8.265 36.625,8.265
  region net GND: 25.8,8.59 25.85,8.64 25.85,8.965 25.75,9.065 25.2,9.065 25,8.865 25,8.69 25.1,8.59

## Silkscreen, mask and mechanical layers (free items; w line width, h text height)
TopOverlay:
  drawing of 631 lines, arcs and shapes, not listed
  text "TCK" at 31.9,14.365 h0.7
  text "TDO" at 34.475,14.365 h0.7
  text "TMS" at 37.125,14.365 h0.7
  text "TDI" at 39.725,14.365 h0.7
  text "VCC1P8" at 42.15,14.365 h0.7
  text "GND" at 29.225,14.34 h0.7
  text "VCC5P0_USB" at 46.775,14.24 h0.7
  text "C" at 4.725,14.19 h1 r90
  text "FPGA JTAG" at 16.825,12.89 h0.7
  text "v1.0" at 5.875,12.765 h1.45 r90
  text "RX" at 67.925,11.715 h1.7 r90
  text "Mini" at 5.875,9.165 h1.45 r90
  text "LimeSDR" at 4.8,7.515 h1.45 r90
  text "FPGA GPIO" at 34.05,5.19 h0.7 r90
  text "USB3.0" at 7.825,1.065 h0.7 r90
  text "LMS7002M" at 38.95,-4.01 h0.9 r90
  text "ALTERA MAX10" at 33.675,-5.085 h0.7 r90
  text "VCC3P3A" at 21.825,-6.735 h0.55
  text "BOM VER" at 30.75,-8.86 h0.55
  text "2" at 29.8,-10.01 h0.55
  text "1" at 29.775,-11.135 h0.55
  text "0" at 29.775,-12.16 h0.55
  text "VCC3P3" at 20.625,-12.335 h0.55 r90
  text "VCC1P8" at 29.725,-12.51 h0.55 r90
  text "FAN" at 4,-13.735 h0.55
  text "GND" at 29.25,-15.46 h0.7
  text "VCC3P3" at 39.3,-15.46 h0.7
  text "VCC1P8" at 44.15,-15.46 h0.7
  text "TX" at 67.925,-15.46 h1.7 r90
  text "VCC" at 1.75,-15.51 h0.55
  text "EGPIO(0-1)" at 32.1,-15.51 h0.7
BottomOverlay:
  drawing of 657 lines, arcs and shapes, not listed
  text "OUT" at 36.65,14.965 h0.55
  text "IN" at 40.975,14.965 h0.55
  text "RX" at 68.775,14.54 h1.7 r90
  text "REF / CLK" at 44.125,7.715 h0.7
  text "TX" at 68.775,-10.91 h1.7 r90
Mechanical1:
  circle w0.2: c2,-12.685 r1
  circle w0.2: c2,12.685 r1
  lines w0.1: 2.025,-20.685 2.025,-15.71 ccw(c2,-15.71) 2,-15.685 ; 2.025,15.71 2.025,20.685 ; 4.3,-20.685 4.3,-15.71 ; 4.3,15.71 4.3,20.685 ; 64.7,-20.685 64.7,-15.71 ; 64.7,15.71 64.7,20.685 ; 66.975,-20.685 66.975,-15.71 ; 66.975,15.71 66.975,20.685 ; 2,-15.685 cw(c2,-13.685) 0,-13.685 0,13.685 cw(c2,13.685) 2,15.685 67,15.685 cw(c67,13.685) 69,13.685 69,-13.685 cw(c67,-13.685) 67,-15.685 2,-15.685
  lines w0.2: 25.023,15.623 ccw(c26.5,15.885) 27.973,15.598 ; 25.027,-15.598 cw(c26.5,-15.885) 27.977,-15.623 ; 55.027,-15.598 cw(c56.5,-15.885) 57.977,-15.623 ; 55.027,15.598 ccw(c56.5,15.885) 57.977,15.623
  text "NOTE: mounting cutout hole radius with the center offset to the outside of the PCB by 0.2mm" at 31,10.915 h0.7
  text "NOTE: mounting hole diameter" at 3.1,6.615 h0.7
  text "Local Fiducial" at 31.65,0.665 h0.7
  text "Vendor logo, date code,  / RoHS (bottom)" at 26.975,-15.385 h0.55
Mechanical2:
  lines w0.2: 69,0 69,52 ; 102,48 ccw(c104,48) 104,46 169,46 ccw(c169,48) 171,48 171,96 ccw(c169,96) 169,98 104,98 ccw(c104,96) 102,96 102,48 ; 102,48 102,48
ASM BOT:
  drawing of 227 lines, arcs and shapes, not listed
  text "Assembly bottom" at 61.675,14.165 h1.25
  text "Assembly note: / LED2 can be mounted  / sticking out of the  / board or not. If mounted,  / the default position is  / sticking out." at 67.6,-15.585 h0.35
ASM TOP:
  lines w0.1: 1.525,-5.835 1.85,-4.585 ; 2.075,5.565 2.7,1.165 ; 8.225,-12.985 9.975,-11.91 ; 15.525,11.015 17.85,10.915 ; 18.55,6.215 19.3,6.94 ; 19,12.115 19.95,10.99 ; 19.2,4.14 20.25,5.24 ; 20.95,6.84 22.7,4.315 ; 22.425,6.465 23.45,5.615 ; 22.875,11.99 22.875,15.065 34.475,15.065 34.475,12.215 ; 32.55,6.365 32.55,12.215 38.575,12.215 38.575,6.365 32.55,6.365
  lines w0.2: 18.025,7.39 18.025,10.115 ; 21.775,7.34 23.6,7.34 23.6,6.315 24.8,6.315 ; 22.2,12.215 24.725,12.215
  lines w0.3: 0,-13.685 ccw(c2,-13.685) 2,-15.685 67,-15.685 ccw(c67,-13.685) 69,-13.685 69,13.685 ccw(c67,13.685) 67,15.685 2,15.685 ccw(c2,13.685) 0,13.685 0,-13.685
  text "Assembly top" at 52.975,14.14 h1.25
  text "ASSEMBLY NOTE: / J7 mechanical mechanical holes must be soldered for mechanical durability." at 6.05,-6.61 h0.55 r90

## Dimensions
2,22.8 to 2,-22.8 on Mechanical1
26.5,15.885 to 31.306,11.079 on Mechanical1
2,12.685 to 2,5.837 on Mechanical1
26.5,14.385 to 26.5,-14.385 on Mechanical1
26.5,-14.385 to 56.5,-14.385 on Mechanical1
